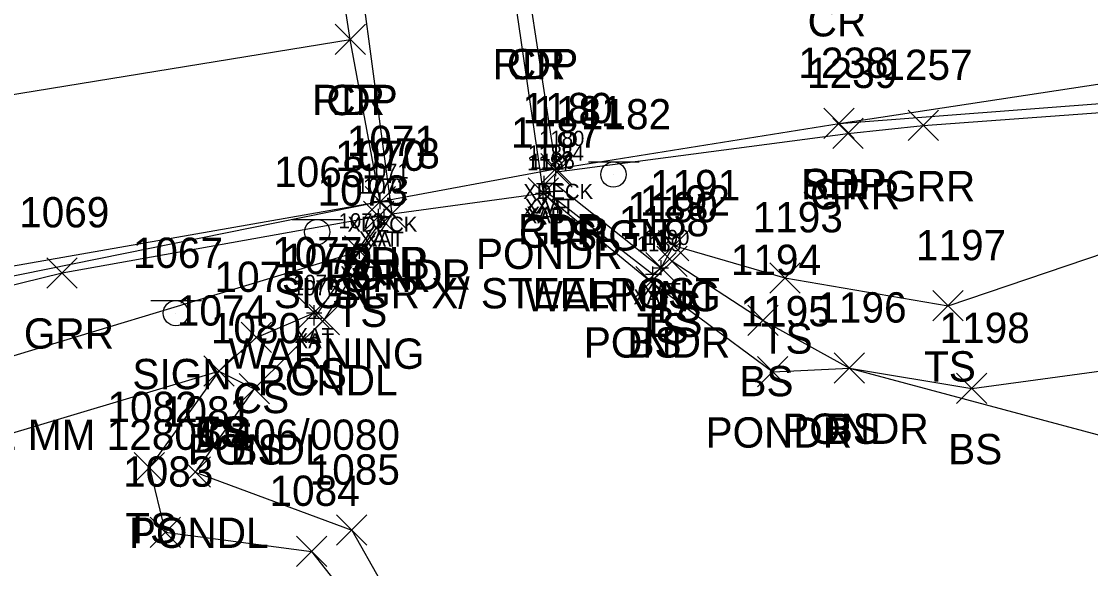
# Model space of a CAD drawing. Extents: x 1497084 to 1499861, y 734741 to 735567.
# Drawn here: x 1498306.3 to 1498376.8, y 735270.8 to 735306.9 of the extents above; entities that cross this region are included whole.
import ezdxf

# ---------------------------------------------------------------- set-up
doc = ezdxf.new("R2010")
doc.units = 0
for name, color, linetype in [('B_A', 7, 'Continuous'), ('B_I', 7, 'Continuous'), ('B_TIC', 7, 'Continuous'), ('BELB', 7, 'Continuous'), ('BSUBM', 7, 'Continuous'), ('L_A', 7, 'Continuous'), ('L_I', 7, 'Continuous'), ('L_TIC', 7, 'Continuous'), ('LAWE', 7, 'Continuous'), ('LELB', 7, 'Continuous'), ('P_A', 7, 'Continuous'), ('P_I', 7, 'Continuous'), ('P_TIC', 7, 'Continuous'), ('PET', 7, 'Continuous'), ('PRC', 7, 'Continuous'), ('PSP', 7, 'Continuous'), ('R_A', 7, 'Continuous'), ('R_C', 7, 'Continuous'), ('R_I', 7, 'Continuous'), ('R_TIC', 7, 'Continuous'), ('RGR', 7, 'Continuous'), ('S_A', 7, 'Continuous'), ('S_C', 7, 'Continuous'), ('S_I', 7, 'Continuous'), ('SSGN', 7, 'Continuous')]:
    doc.layers.add(name, color=color, linetype=linetype)

msp = doc.modelspace()

# ---------------------------------------------------------------- linework, layer by layer
at = {"layer": 'B_TIC'}
for p, q in [((1498341.544, 735297.196), (1498341.62, 735297.196)), ((1498340.77, 735296.228), (1498340.845, 735296.228)), ((1498341.468, 735296.226), (1498341.543, 735296.226)), ((1498341.468, 735296.226), (1498341.543, 735296.226)), ((1498340.7, 735295.582), (1498340.776, 735295.582)), ((1498340.899, 735295.684), (1498340.974, 735295.684)), ((1498329.954, 735295.031), (1498330.03, 735295.031)), ((1498329.847, 735294.053), (1498329.923, 735294.053)), ((1498330.208, 735294.046), (1498330.283, 735294.046)), ((1498328.597, 735291.758), (1498328.673, 735291.758)), ((1498348.471, 735290.662), (1498348.547, 735290.662)), ((1498348.471, 735290.662), (1498348.547, 735290.662)), ((1498347.937, 735290.239), (1498348.012, 735290.239)), ((1498325.599, 735287.696), (1498325.674, 735287.696)), ((1498325.609, 735287.341), (1498325.684, 735287.341))]:
    msp.add_line(p, q, dxfattribs=at)
for points in [[(1498341.541, 735296.696), (1498341.541, 735297.696)], [(1498340.766, 735295.728), (1498340.766, 735296.728)], [(1498341.041, 735297.196), (1498342.041, 735297.196)], [(1498341.464, 735295.726), (1498341.464, 735296.726)], [(1498341.464, 735295.726), (1498341.464, 735296.726)], [(1498340.266, 735296.228), (1498341.266, 735296.228)], [(1498340.697, 735295.082), (1498340.697, 735296.082)], [(1498340.895, 735295.184), (1498340.895, 735296.184)], [(1498340.964, 735296.226), (1498341.964, 735296.226)], [(1498340.964, 735296.226), (1498341.964, 735296.226)], [(1498329.951, 735294.531), (1498329.951, 735295.531)], [(1498340.197, 735295.582), (1498341.197, 735295.582)], [(1498340.395, 735295.684), (1498341.395, 735295.684)], [(1498329.451, 735295.031), (1498330.451, 735295.031)], [(1498329.344, 735294.053), (1498330.344, 735294.053)], [(1498329.704, 735294.046), (1498330.704, 735294.046)], [(1498329.844, 735293.553), (1498329.844, 735294.553)], [(1498330.204, 735293.546), (1498330.204, 735294.546)], [(1498328.094, 735291.758), (1498329.094, 735291.758)], [(1498328.594, 735291.258), (1498328.594, 735292.258)], [(1498348.468, 735290.162), (1498348.468, 735291.162)], [(1498348.468, 735290.162), (1498348.468, 735291.162)], [(1498347.933, 735289.739), (1498347.933, 735290.739)], [(1498347.968, 735290.662), (1498348.968, 735290.662)], [(1498347.968, 735290.662), (1498348.968, 735290.662)], [(1498347.433, 735290.239), (1498348.433, 735290.239)], [(1498325.095, 735287.696), (1498326.095, 735287.696)], [(1498325.595, 735287.196), (1498325.595, 735288.196)], [(1498325.605, 735286.841), (1498325.605, 735287.841)], [(1498325.105, 735287.341), (1498326.105, 735287.341)]]:
    msp.add_lwpolyline(points, dxfattribs=at)
at = {"layer": 'BELB'}
msp.add_lwpolyline([(1498329.951, 735295.031), (1498341.541, 735297.196)], dxfattribs=at)
at = {"layer": 'BSUBM'}
for points in [[(1498337.164, 735325.038), (1498337.56, 735327.025), (1498335.887, 735326.633), (1498337.201, 735319.55), (1498340.697, 735295.582)], [(1498327.482, 735318.469), (1498330.708, 735294.208)], [(1498341.464, 735296.226), (1498340.766, 735296.228), (1498340.895, 735295.684), (1498347.933, 735290.239), (1498348.468, 735290.662)], [(1498341.464, 735296.226), (1498348.468, 735290.662)], [(1498329.844, 735294.053), (1498330.204, 735294.046), (1498328.594, 735291.758), (1498325.605, 735287.341), (1498325.595, 735287.696)]]:
    msp.add_lwpolyline(points, dxfattribs=at)
at = {"layer": 'L_TIC'}
for points in [[(1498339.697, 735294.582), (1498341.697, 735296.582)], [(1498341.697, 735294.582), (1498339.697, 735296.582)], [(1498329.708, 735293.208), (1498331.708, 735295.208)], [(1498331.708, 735293.208), (1498329.708, 735295.208)], [(1498329.708, 735293.208), (1498331.708, 735295.208)], [(1498331.708, 735293.208), (1498329.708, 735295.208)], [(1498327.594, 735290.758), (1498329.594, 735292.758)], [(1498329.594, 735290.758), (1498327.594, 735292.758)], [(1498348.296, 735291.118), (1498350.296, 735293.118)], [(1498350.296, 735291.118), (1498348.296, 735293.118)], [(1498348.192, 735290.091), (1498350.192, 735292.091)], [(1498350.192, 735290.091), (1498348.192, 735292.091)], [(1498347.468, 735289.662), (1498349.468, 735291.662)], [(1498349.468, 735289.662), (1498347.468, 735291.662)], [(1498346.808, 735288.734), (1498348.808, 735290.734)], [(1498348.808, 735288.734), (1498346.808, 735290.734)], [(1498346.808, 735288.734), (1498348.808, 735290.734)], [(1498348.808, 735288.734), (1498346.808, 735290.734)], [(1498355.634, 735288.995), (1498357.634, 735290.995)], [(1498357.634, 735288.995), (1498355.634, 735290.995)], [(1498366.396, 735287.155), (1498368.396, 735289.155)], [(1498368.396, 735287.155), (1498366.396, 735289.155)], [(1498324.595, 735286.696), (1498326.595, 735288.696)], [(1498326.595, 735286.696), (1498324.595, 735288.696)], [(1498325.26, 735286.239), (1498327.26, 735288.239)], [(1498327.26, 735286.239), (1498325.26, 735288.239)], [(1498354.192, 735286.185), (1498356.192, 735288.185)], [(1498356.192, 735286.185), (1498354.192, 735288.185)], [(1498320.794, 735285.068), (1498322.794, 735287.068)], [(1498322.794, 735285.068), (1498320.794, 735287.068)], [(1498318.312, 735282.844), (1498320.312, 735284.844)], [(1498320.312, 735282.844), (1498318.312, 735284.844)], [(1498318.312, 735282.844), (1498320.312, 735284.844)], [(1498320.312, 735282.844), (1498318.312, 735284.844)], [(1498318.312, 735282.844), (1498320.312, 735284.844)], [(1498320.312, 735282.844), (1498318.312, 735284.844)], [(1498354.835, 735282.797), (1498356.835, 735284.797)], [(1498356.835, 735282.797), (1498354.835, 735284.797)], [(1498359.889, 735283.044), (1498361.889, 735285.044)], [(1498361.889, 735283.044), (1498359.889, 735285.044)], [(1498359.889, 735283.044), (1498361.889, 735285.044)], [(1498361.889, 735283.044), (1498359.889, 735285.044)], [(1498320.641, 735281.678), (1498322.641, 735283.678)], [(1498322.641, 735281.678), (1498320.641, 735283.678)], [(1498320.641, 735281.678), (1498322.641, 735283.678)], [(1498322.641, 735281.678), (1498320.641, 735283.678)], [(1498367.956, 735281.699), (1498369.956, 735283.699)], [(1498369.956, 735281.699), (1498367.956, 735283.699)], [(1498313.735, 735276.483), (1498315.735, 735278.483)], [(1498315.735, 735276.483), (1498313.735, 735278.483)], [(1498316.757, 735276.18), (1498318.757, 735278.18)], [(1498318.757, 735276.18), (1498316.757, 735278.18)], [(1498314.773, 735272.218), (1498316.773, 735274.218)], [(1498316.773, 735272.218), (1498314.773, 735274.218)], [(1498327.071, 735272.353), (1498329.071, 735274.353)], [(1498329.071, 735272.353), (1498327.071, 735274.353)], [(1498324.423, 735270.952), (1498326.423, 735272.952)], [(1498326.423, 735270.952), (1498324.423, 735272.952)]]:
    msp.add_lwpolyline(points, dxfattribs=at)
at = {"layer": 'LAWE'}
for points in [[(1498330.708, 735294.208), (1498340.697, 735295.582), (1498347.808, 735289.734), (1498355.835, 735283.797), (1498360.889, 735284.044), (1498388.96, 735276.515), (1498404.752, 735283.124), (1498435.911, 735287.743), (1498448.584, 735273.781), (1498443.339, 735255.806), (1498425.709, 735252.418), (1498412.053, 735248.321), (1498401.028, 735256.308), (1498395.487, 735265.648), (1498382.914, 735267.989), (1498367.49, 735259.738), (1498377.453, 735246.793), (1498383.142, 735228.324)], [(1498330.708, 735294.208), (1498326.26, 735287.239), (1498321.641, 735282.678), (1498317.757, 735277.18), (1498328.071, 735273.353), (1498333.814, 735263.196), (1498337.234, 735253.726), (1498331.058, 735237.113)]]:
    msp.add_lwpolyline(points, dxfattribs=at)
at = {"layer": 'LELB'}
for points in [[(1498348.468, 735290.662), (1498349.296, 735292.118), (1498356.634, 735289.995), (1498367.396, 735288.155), (1498383.016, 735293.443), (1498402.409, 735293.849), (1498412.25, 735297.618), (1498434.814, 735303.591), (1498479.542, 735310.526), (1498504.668, 735314.809), (1498560.972, 735322.474), (1498619.672, 735330.556), (1498677.124, 735338.581), (1498739.343, 735349.098), (1498794.83, 735357.086), (1498843.562, 735364.403), (1498863.08, 735369.391)], [(1498347.808, 735289.734), (1498349.192, 735291.091), (1498355.192, 735287.185), (1498360.889, 735284.044), (1498368.956, 735282.699), (1498386.861, 735285.137), (1498402.115, 735288.931), (1498434.544, 735297.051), (1498479.168, 735305.56), (1498505.43, 735311.828), (1498561.532, 735319.258), (1498619.714, 735327.595), (1498677.773, 735335.72), (1498739.773, 735346.921), (1498794.896, 735353.463), (1498843.96, 735361.064), (1498867.571, 735365.181)], [(1498171.921, 735256.289), (1498211.53, 735265.457), (1498254.937, 735273.438), (1498271.69, 735272.78), (1498298.74, 735282.744), (1498328.594, 735291.758)], [(1498319.312, 735283.844), (1498321.794, 735286.068), (1498325.595, 735287.696)], [(1498172.325, 735251.623), (1498210.713, 735260.44), (1498256.694, 735269.546), (1498270.406, 735267.796), (1498298.449, 735277.604), (1498319.312, 735283.844), (1498321.641, 735282.678)], [(1498319.312, 735283.844), (1498314.735, 735277.483), (1498315.773, 735273.218), (1498325.423, 735271.952), (1498331.729, 735263.937), (1498335.133, 735254.496), (1498327.808, 735238.222)]]:
    msp.add_lwpolyline(points, dxfattribs=at)
at = {"layer": 'P_TIC'}
for points in [[(1498326.972, 735304.727), (1498328.972, 735306.727)], [(1498328.972, 735304.727), (1498326.972, 735306.727)], [(1498326.972, 735304.727), (1498328.972, 735306.727)], [(1498328.972, 735304.727), (1498326.972, 735306.727)], [(1498359.209, 735299.184), (1498361.209, 735301.184)], [(1498361.209, 735299.184), (1498359.209, 735301.184)], [(1498359.209, 735299.184), (1498361.209, 735301.184)], [(1498361.209, 735299.184), (1498359.209, 735301.184)], [(1498340.541, 735296.196), (1498342.541, 735298.196)], [(1498342.541, 735296.196), (1498340.541, 735298.196)], [(1498328.951, 735294.031), (1498330.951, 735296.031)], [(1498330.951, 735294.031), (1498328.951, 735296.031)], [(1498328.951, 735294.031), (1498330.951, 735296.031)], [(1498330.951, 735294.031), (1498328.951, 735296.031)]]:
    msp.add_lwpolyline(points, dxfattribs=at)
at = {"layer": 'PET'}
for points in [[(1498338.165, 735318.882), (1498339.87, 735308.098), (1498341.541, 735297.196), (1498360.209, 735300.184), (1498403.131, 735306.703), (1498454.967, 735313.532), (1498504.375, 735320.924), (1498560.617, 735329.108), (1498618.152, 735338.15), (1498676.466, 735346.785), (1498736.788, 735356.316), (1498793.849, 735365.136), (1498842.44, 735373.21), (1498892.667, 735381.868)], [(1498170.524, 735263.099), (1498210.239, 735272.243), (1498264.155, 735283.497), (1498329.951, 735295.031), (1498327.972, 735305.727), (1498326.235, 735317.05)]]:
    msp.add_lwpolyline(points, dxfattribs=at)
at = {"layer": 'PRC'}
msp.add_lwpolyline([(1498167.477, 735273.955), (1498208.545, 735283.499), (1498261.915, 735294.085), (1498300.302, 735301.207), (1498327.972, 735305.727)], dxfattribs=at)
at = {"layer": 'PSP'}
for points in [[(1498360.209, 735300.184), (1498403.505, 735303.499), (1498455.725, 735308.977), (1498504.765, 735316.344), (1498560.606, 735324.722), (1498619.041, 735333.453), (1498677.107, 735341.572), (1498738.317, 735351.548), (1498794.377, 735360.626), (1498843.609, 735368.572), (1498860.461, 735371.228)], [(1498171.243, 735258.372), (1498211.203, 735267.714), (1498264.028, 735280.235), (1498282.639, 735285.438), (1498329.951, 735295.031)]]:
    msp.add_lwpolyline(points, dxfattribs=at)
at = {"layer": 'R_TIC'}
for points in [[(1498364.752, 735299.05), (1498366.752, 735301.05)], [(1498366.752, 735299.05), (1498364.752, 735301.05)], [(1498359.793, 735298.518), (1498361.793, 735300.518)], [(1498361.793, 735298.518), (1498359.793, 735300.518)], [(1498340.606, 735295.979), (1498342.606, 735297.979)], [(1498342.606, 735295.979), (1498340.606, 735297.979)], [(1498328.844, 735293.053), (1498330.844, 735295.053)], [(1498330.844, 735293.053), (1498328.844, 735295.053)], [(1498307.971, 735289.323), (1498309.971, 735291.323)], [(1498309.971, 735289.323), (1498307.971, 735291.323)]]:
    msp.add_lwpolyline(points, dxfattribs=at)
at = {"layer": 'RGR'}
for points in [[(1498341.606, 735296.979), (1498360.793, 735299.518), (1498365.752, 735300.05), (1498391.841, 735301.959), (1498404.458, 735299.963)], [(1498269.639, 735277.41), (1498280.806, 735283.396), (1498308.971, 735290.323), (1498329.844, 735294.053)]]:
    msp.add_lwpolyline(points, dxfattribs=at)
at = {"layer": 'SSGN'}
for p, q in [((1498343.682, 735297.643), (1498347.016, 735297.643)), ((1498345.329, 735296.809), (1498345.329, 735296.809)), ((1498324.15, 735293.848), (1498327.483, 735293.848)), ((1498325.797, 735293.015), (1498325.797, 735293.015)), ((1498314.829, 735288.502), (1498318.162, 735288.502)), ((1498316.475, 735287.668), (1498316.475, 735287.668))]:
    msp.add_line(p, q, dxfattribs=at)
for centre in [(1498345.329, 735296.809), (1498325.797, 735293.015), (1498316.475, 735287.668)]:
    msp.add_circle(centre, 0.833, dxfattribs=at)

# ---------------------------------------------------------------- texts
at = {"layer": 'B_A'}
for s, p in [('XDECK', (1498339.383, 735295.196)), ('XAB', (1498339.417, 735293.582)), ('XAT', (1498339.471, 735294.228)), ('XAT', (1498339.6, 735293.684)), ('XAT', (1498340.169, 735294.226)), ('XAT', (1498340.169, 735294.226)), ('XDECK', (1498327.793, 735293.031)), ('XAT', (1498328.548, 735292.053)), ('XAT', (1498328.909, 735292.046)), ('XAT', (1498327.298, 735289.758)), ('XAT', (1498347.173, 735288.662)), ('XAT', (1498347.173, 735288.662)), ('XAT', (1498346.638, 735288.239)), ('XAT', (1498324.3, 735285.696)), ('XAT', (1498324.31, 735285.341))]:
    msp.add_text(s, height=1, dxfattribs=at).set_placement(p)
at = {"layer": 'B_I'}
for s, p in [('1180', (1498340.434, 735298.696)), ('1187', (1498339.634, 735297.082)), ('1185', (1498339.703, 735297.728)), ('1186', (1498339.805, 735297.184)), ('1184', (1498340.401, 735297.726)), ('1184', (1498340.401, 735297.726)), ('1071', (1498328.848, 735296.531)), ('1070', (1498328.414, 735295.553)), ('1072', (1498328.818, 735295.546)), ('1073', (1498327.208, 735293.258)), ('1190', (1498347.362, 735292.162)), ('1190', (1498347.362, 735292.162)), ('1189', (1498346.866, 735291.739)), ('1076', (1498324.192, 735288.841)), ('1077', (1498324.209, 735289.196))]:
    msp.add_text(s, height=1, dxfattribs=at).set_placement(p)
at = {"layer": 'L_A'}
for s, p in [('PONDR', (1498336.264, 735290.582)), ('PONDR', (1498326.274, 735289.208)), ('PONDL', (1498326.33, 735289.208)), ('TS', (1498347.706, 735287.118)), ('TS', (1498327.003, 735286.758)), ('TS', (1498346.877, 735285.662)), ('BS', (1498347.633, 735286.091)), ('TS', (1498355.043, 735284.995)), ('PONDR', (1498343.375, 735284.734)), ('BS', (1498346.249, 735284.734)), ('CS', (1498324.036, 735282.696)), ('TS', (1498365.805, 735283.155)), ('PONDL', (1498321.882, 735282.239)), ('BS', (1498353.633, 735282.185)), ('CS', (1498320.235, 735281.068)), ('TS', (1498317.721, 735278.844)), ('CS', (1498317.753, 735278.844)), ('BS', (1498317.753, 735278.844)), ('PONDR', (1498351.402, 735278.797)), ('PONDR', (1498356.456, 735279.044)), ('BS', (1498359.33, 735279.044)), ('PONDL', (1498317.263, 735277.678)), ('BS', (1498320.082, 735277.678)), ('BS', (1498367.397, 735277.699)), ('TS', (1498313.145, 735272.483)), ('PONDL', (1498313.379, 735272.18))]:
    msp.add_text(s, height=2, dxfattribs=at).set_placement(p)
at = {"layer": 'L_I'}
for s, p in [('1187', (1498338.571, 735298.582)), ('1078', (1498327.936, 735297.208)), ('1078', (1498327.936, 735297.208)), ('1073', (1498325.822, 735294.758)), ('1191', (1498347.737, 735295.118)), ('1192', (1498347.066, 735294.091)), ('1190', (1498346.255, 735293.662)), ('1188', (1498345.682, 735292.734)), ('1188', (1498345.682, 735292.734)), ('1193', (1498354.508, 735292.995)), ('1197', (1498365.27, 735291.155)), ('1077', (1498322.823, 735290.696)), ('1079', (1498323.481, 735290.239)), ('1194', (1498353.066, 735290.185)), ('1075', (1498319.022, 735289.068)), ('1196', (1498358.708, 735287.044)), ('1196', (1498358.708, 735287.044)), ('1074', (1498316.54, 735286.844)), ('1074', (1498316.54, 735286.844)), ('1074', (1498316.54, 735286.844)), ('1195', (1498353.709, 735286.797)), ('1080', (1498318.783, 735285.678)), ('1080', (1498318.783, 735285.678)), ('1198', (1498366.83, 735285.699)), ('1082', (1498311.964, 735280.483)), ('1081', (1498315.552, 735280.18)), ('1085', (1498325.3, 735276.353)), ('1083', (1498313.001, 735276.218)), ('1084', (1498322.651, 735274.952))]:
    msp.add_text(s, height=2, dxfattribs=at).set_placement(p)
at = {"layer": 'P_A'}
for s, p in [('CR', (1498358.134, 735305.919)), ('RDP', (1498337.358, 735303.098)), ('CR', (1498338.303, 735303.098)), ('RDP', (1498325.46, 735300.727)), ('CR', (1498326.405, 735300.727)), ('SHP', (1498357.745, 735295.184)), ('RDP', (1498357.697, 735295.184)), ('RDP', (1498339.029, 735292.196)), ('SHP', (1498327.486, 735290.031)), ('RDP', (1498327.439, 735290.031))]:
    msp.add_text(s, height=2, dxfattribs=at).set_placement(p)
at = {"layer": 'P_I'}
for s, p in [('1238', (1498357.516, 735303.184)), ('1238', (1498357.516, 735303.184)), ('1180', (1498339.328, 735300.196)), ('1071', (1498327.746, 735298.031)), ('1071', (1498327.746, 735298.031))]:
    msp.add_text(s, height=2, dxfattribs=at).set_placement(p)
at = {"layer": 'R_A'}
for p in [(1498363.24, 735295.05), (1498358.281, 735294.518), (1498339.094, 735291.979), (1498327.332, 735289.053), (1498306.459, 735285.323)]:
    msp.add_text('GRR', height=2, dxfattribs=at).set_placement(p)
at = {"layer": 'R_C'}
msp.add_text('SGR X/ STEELPOST', height=2, dxfattribs=at).set_placement((1498326.779, 735287.979))
at = {"layer": 'R_I'}
for s, p in [('1239', (1498358.092, 735302.518)), ('1257', (1498363.059, 735303.05)), ('1181', (1498340.047, 735299.979)), ('1070', (1498326.985, 735297.053)), ('1069', (1498306.144, 735293.323))]:
    msp.add_text(s, height=2, dxfattribs=at).set_placement(p)
at = {"layer": 'S_A'}
for p in [(1498342.467, 735291.789), (1498322.935, 735287.995), (1498313.613, 735282.648)]:
    msp.add_text('SIGN', height=2, dxfattribs=at).set_placement(p)
at = {"layer": 'S_C'}
for s, p in [('WARNING', (1498339.475, 735287.789)), ('WARNING', (1498319.943, 735283.995)), ('VT128/BR2 MM 1280/0406/0080', (1498292.149, 735278.648))]:
    msp.add_text(s, height=2, dxfattribs=at).set_placement(p)
at = {"layer": 'S_I'}
for s, p in [('1182', (1498343.184, 735299.789)), ('1068', (1498322.958, 735295.995)), ('1067', (1498313.637, 735290.648))]:
    msp.add_text(s, height=2, dxfattribs=at).set_placement(p)

doc.saveas('drawing.dxf')
